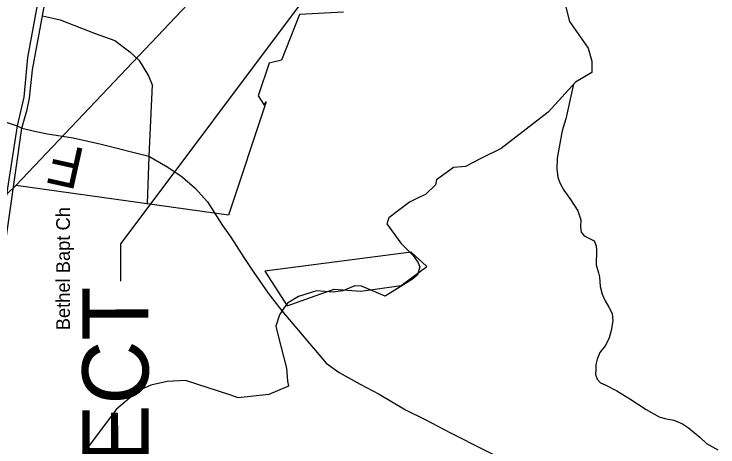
# Model space of a CAD drawing. Extents: x 1373043 to 1375788, y 550128 to 553055.
# Drawn here: x 1373215 to 1373347.9, y 550507.8 to 550589.5 of the extents above; entities that cross this region are included whole.
import ezdxf

# ---------------------------------------------------------------- set-up
doc = ezdxf.new("R2010")
doc.units = 0
for name, color, linetype in [('Default', 7, 'Continuous'), ('Old_Level_22', 7, 'Continuous'), ('Old_Level_28', 7, 'Continuous'), ('Old_Level_32', 7, 'Continuous'), ('Old_Level_48', 7, 'Continuous'), ('Old_Level_50', 7, 'Continuous'), ('Old_Level_59', 7, 'Continuous'), ('Old_Level_62', 7, 'Continuous'), ('Prop Dimension', 7, 'Continuous')]:
    doc.layers.add(name, color=color, linetype=linetype)

msp = doc.modelspace()

# ---------------------------------------------------------------- linework, layer by layer
at = {"layer": 'Old_Level_28'}
for points in [[(1373226.06, 550631.31), (1373225.64, 550628.34), (1373223.71, 550615.87), (1373222.54, 550608.9), (1373220.58, 550598.62), (1373219.35, 550591.16), (1373217.56, 550581.32), (1373216.87, 550573.83), (1373215.59, 550568.43)], [(1373220.41, 550589.14), (1373227.56, 550628.71), (1373228, 550631.12)], [(1373216.5, 550567.93), (1373217.51, 550571.48), (1373217.94, 550573.63), (1373218.5, 550578.96), (1373220.41, 550589.14)], [(1373215.59, 550568.43), (1373212.24, 550547.34), (1373209.86, 550535.6), (1373208.94, 550529.37), (1373205.78, 550510.18)], [(1373207.13, 550509.66), (1373210.68, 550530.39), (1373212.28, 550538.81), (1373213.04, 550543.58), (1373216.5, 550567.93)]]:
    msp.add_lwpolyline(points, dxfattribs=at)
at = {"layer": 'Old_Level_32'}
for p, q in [((1373215.59, 550568.43), (1373216.5, 550567.93)), ((1373240.43, 550562.66), (1373240.15, 550553.67))]:
    msp.add_line(p, q, dxfattribs=at)
for points in [[(1373220.41, 550589.14), (1373223.69, 550588.37), (1373230.34, 550585.81), (1373234.02, 550584.48), (1373236.88, 550582.34), (1373238.62, 550580.7), (1373240.36, 550577.84), (1373241.09, 550576.13), (1373240.43, 550562.66)], [(1373174.59, 550577.91), (1373177.17, 550577.35), (1373189.05, 550574.73), (1373210.57, 550569.65), (1373213.69, 550569.02), (1373215.59, 550568.43)], [(1373216.5, 550567.93), (1373219.16, 550567.31), (1373221.33, 550566.9), (1373226.19, 550566.11), (1373231.22, 550564.99), (1373240.43, 550562.66)], [(1373240.43, 550562.66), (1373244.01, 550560.61), (1373246.72, 550558.76), (1373249.19, 550556.67), (1373251.53, 550554.08), (1373254.36, 550549.59), (1373255.95, 550547.42), (1373258.35, 550543.57), (1373260.14, 550540.89), (1373262.98, 550536.85), (1373265.54, 550533.49)], [(1373265.54, 550533.49), (1373273.89, 550523.64), (1373276.39, 550521.83), (1373280.32, 550519.63), (1373283.94, 550517.74), (1373288.92, 550514.81), (1373292.62, 550512.97), (1373297.36, 550510.49), (1373310, 550504.11)]]:
    msp.add_lwpolyline(points, dxfattribs=at)
at = {"layer": 'Old_Level_48'}
for p, q in [((1373215.37, 550557.12), (1373271.25, 550616.15)), ((1373268.91, 550589.41), (1373265.49, 550580.8)), ((1373277.18, 550589.86), (1373268.91, 550589.41)), ((1373265.49, 550580.8), (1373263.18, 550580.23)), ((1373263.18, 550580.23), (1373261.06, 550574.06)), ((1373261.06, 550574.06), (1373262.22, 550572.33)), ((1373262.6, 550572.91), (1373255.47, 550551.54)), ((1373262.22, 550572.33), (1373262.6, 550572.91)), ((1373196.29, 550539.02), (1373215.37, 550557.12)), ((1373255.47, 550551.54), (1373215.37, 550557.12)), ((1373262.33, 550540.99), (1373266.55, 550534.45))]:
    msp.add_line(p, q, dxfattribs=at)
msp.add_lwpolyline([(1373266.55, 550534.45), (1373271.83, 550536.35), (1373275.41, 550537.61), (1373280.47, 550537.19), (1373288.07, 550538.25), (1373292.92, 550541.83), (1373289.96, 550544.57), (1373262.33, 550540.99)], dxfattribs=at)
at = {"layer": 'Old_Level_50'}
msp.add_line((1373265.56, 550533.53), (1373265.56, 550533.53), dxfattribs=at)
at = {"layer": 'Old_Level_59'}
for points in [[(1373319.06, 550591.07), (1373319.87, 550588.1), (1373323.36, 550583.07), (1373324.08, 550580.59), (1373324.08, 550578.48), (1373320.95, 550576.64), (1373315.82, 550570.98), (1373306.92, 550564.15), (1373303.24, 550562.27), (1373300.23, 550560.75), (1373299.51, 550560.66), (1373297.98, 550560.57), (1373294.75, 550558.23), (1373294.57, 550557.24), (1373292.68, 550555.45), (1373291.51, 550554.91), (1373289.62, 550554.01), (1373285.76, 550551.04), (1373285.4, 550549.88), (1373288.01, 550546.28), (1373290.34, 550543.95), (1373291.24, 550542.69), (1373291.6, 550541.79)], [(1373291.6, 550541.79), (1373291.15, 550540.27), (1373290.22, 550539.47), (1373285.08, 550536.27), (1373280.61, 550538.15), (1373279.34, 550538.23), (1373277.05, 550537.24), (1373275.24, 550536.99), (1373272.12, 550537.27), (1373268.67, 550536.23), (1373266.64, 550534.93), (1373265.71, 550533.73), (1373265.08, 550532.74), (1373264.41, 550530.61), (1373264.89, 550528.8), (1373266.41, 550522.7), (1373266.64, 550520.21), (1373266.79, 550519.31), (1373263.09, 550517.73), (1373257.34, 550517.05), (1373255.72, 550517.66), (1373247.39, 550520.34), (1373243.9, 550520.19), (1373240.85, 550519.47), (1373238.41, 550518.39), (1373234.34, 550514.91), (1373223.48, 550500.46)]]:
    msp.add_lwpolyline(points, dxfattribs=at)
at = {"layer": 'Old_Level_62'}
msp.add_lwpolyline([(1373320.59, 550576.25), (1373319.16, 550569.73), (1373318.49, 550567.48), (1373317.91, 550564.4), (1373317.51, 550562.27), (1373317.47, 550560.31), (1373317.67, 550558.73), (1373318.04, 550557.66), (1373318.76, 550556.26), (1373320.04, 550554.53), (1373321.39, 550552.36), (1373321.98, 550550.64), (1373321.95, 550549.26), (1373322.06, 550548.31), (1373322.62, 550547.66), (1373323.62, 550547.14), (1373324.48, 550546.68), (1373324.91, 550545.73), (1373324.97, 550544.91), (1373324.89, 550542.2), (1373325.3, 550540.68), (1373325.49, 550539.92), (1373325.63, 550538.08), (1373325.99, 550536.63), (1373326.58, 550535.36), (1373327.26, 550534.21), (1373327.93, 550532.99), (1373328.01, 550531.61), (1373327.74, 550529.78), (1373327.32, 550528.41), (1373326.67, 550526.97), (1373325.56, 550525.61), (1373325.09, 550524.36), (1373324.82, 550523.35), (1373324.8, 550522.41), (1373324.73, 550521.47), (1373325.07, 550520.57), (1373325.7, 550519.93), (1373326.58, 550519.54), (1373328.75, 550518.42), (1373331.25, 550516.91), (1373334.29, 550514.9), (1373336.79, 550513.52), (1373337.85, 550513.19), (1373339.55, 550512.84), (1373341.16, 550512.17), (1373342.28, 550511.4), (1373344.44, 550509.65), (1373345.69, 550508.49), (1373347.86, 550507.24)], dxfattribs=at)
at = {"layer": 'Prop Dimension'}
for p in [(1373307.53, 550642.77), (1373235.15, 550539.09)]:
    msp.add_line(p, (1373235.14, 550546.23), dxfattribs=at)

# ---------------------------------------------------------------- texts
at = {"layer": 'Default'}
msp.add_text('END PROJECT', height=12.4955, rotation=90.0509, dxfattribs=at).set_placement((1373240.48, 550420.18))
at = {"layer": 'Old_Level_22'}
for s, height, rotation, p in [('F', 7.75, 167.4811, (1373228.73, 550563.95)), ('Bethel Bapt Ch', 2.5837, 90, (1373225.55, 550529.83))]:
    msp.add_text(s, height=height, rotation=rotation, dxfattribs=at).set_placement(p)

doc.saveas('drawing.dxf')
